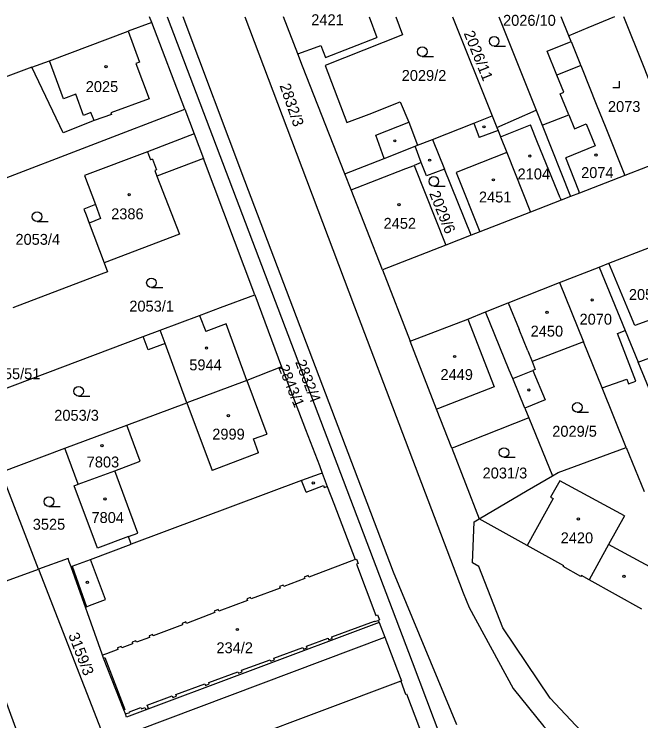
# Model space of a CAD drawing. Extents: x -564952 to -564307, y -1202373 to -1201847.
# Drawn here: x -564730.1 to -564632.5, y -1201959.8 to -1201849.7 of the extents above; entities that cross this region are included whole.
import ezdxf

# ---------------------------------------------------------------- set-up
doc = ezdxf.new("R2010")
doc.units = 0
for name, color, linetype in [('Hranice parcel', 7, 'Continuous'), ('Parcelní čísla', 7, 'Continuous'), ('Vnitřní kresba', 7, 'Continuous'), ('Značky budov', 7, 'Continuous'), ('Značky kultur', 7, 'Continuous')]:
    doc.layers.add(name, color=color, linetype=linetype)

msp = doc.modelspace()

# ---------------------------------------------------------------- linework, layer by layer
at = {"layer": 'Hranice parcel'}
for p, q in [((-564708.7, -1201850.95), (-564709.04, -1201850.07)), ((-564706.28, -1201850.07), (-564668.12, -1201950.64)), ((-564694.16, -1201875.63), (-564703.8, -1201850.07)), ((-564694.18, -1201850.07), (-564686.16, -1201871.23)), ((-564661.81, -1201850.07), (-564655.61, -1201865.52)), ((-564654.61, -1201850.07), (-564648.79, -1201864.64)), ((-564643.69, -1201853.02), (-564644.88, -1201850.07)), ((-564708.7, -1201850.95), (-564712.36, -1201852.32)), ((-564703.52, -1201864.46), (-564708.7, -1201850.95)), ((-564724.64, -1201856.92), (-564712.36, -1201852.32)), ((-564712.36, -1201852.32), (-564710.6, -1201857.14)), ((-564643.32, -1201853.94), (-564643.69, -1201853.02)), ((-564727.38, -1201857.94), (-564724.64, -1201856.92)), ((-564737.23, -1201877.39), (-564703.52, -1201864.46)), ((-564703.52, -1201864.46), (-564702.07, -1201868.33)), ((-564654.9, -1201867.35), (-564648.79, -1201864.64)), ((-564648.79, -1201864.64), (-564647.86, -1201866.96)), ((-564655.61, -1201865.52), (-564654.9, -1201867.35)), ((-564647.86, -1201866.96), (-564643.4, -1201878.11)), ((-564702.07, -1201868.33), (-564709.37, -1201871.11)), ((-564702.07, -1201868.33), (-564700.62, -1201872.17)), ((-564667.27, -1201870.1), (-564664.94, -1201869.19)), ((-564664.94, -1201869.19), (-564663.07, -1201873.83)), ((-564692.64, -1201893.4), (-564700.62, -1201872.17)), ((-564658.92, -1201884.13), (-564663.07, -1201873.83)), ((-564658.92, -1201884.13), (-564662.87, -1201885.69)), ((-564662.87, -1201885.69), (-564672.74, -1201889.5)), ((-564672.74, -1201889.5), (-564668.43, -1201900.65)), ((-564645.16, -1201891.48), (-564638.96, -1201889.11)), ((-564645.16, -1201891.48), (-564641.39, -1201900.77)), ((-564692.64, -1201893.4), (-564688.47, -1201904.65)), ((-564736.45, -1201909.86), (-564710.02, -1201899.92)), ((-564703.22, -1201910.26), (-564706.62, -1201900.99)), ((-564632.88, -1201903.92), (-564624.54, -1201900.73)), ((-564625.61, -1201921.62), (-564632.88, -1201903.92)), ((-564712.58, -1201913.74), (-564703.22, -1201910.26)), ((-564650.53, -1201911.09), (-564649.91, -1201912.6)), ((-564649.91, -1201912.6), (-564646.22, -1201921.62)), ((-564722.24, -1201917.34), (-564712.58, -1201913.74)), ((-564732.16, -1201921.04), (-564722.24, -1201917.34)), ((-564720.15, -1201922.96), (-564722.24, -1201917.34)), ((-564661.94, -1201917.34), (-564657.66, -1201928.36)), ((-564634.72, -1201917.22), (-564631.93, -1201924.07)), ((-564726.36, -1201936.19), (-564732.16, -1201921.04)), ((-564720.15, -1201922.96), (-564714.47, -1201920.84)), ((-564650.19, -1201932.49), (-564657.66, -1201928.36)), ((-564711.89, -1201932.3), (-564712.33, -1201931.11)), ((-564721.74, -1201934.52), (-564726.36, -1201936.19)), ((-564673.25, -1201944.51), (-564672.37, -1201946.79)), ((-564668.12, -1201950.64), (-564653.5, -1201989.14))]:
    msp.add_line(p, q, dxfattribs=at)
for points in [[(-564678.6, -1201874.56), (-564685.18, -1201857.76), (-564685.91, -1201855.87), (-564688.16, -1201850.07)], [(-564670.64, -1201850.07), (-564669.6, -1201852.87), (-564681.68, -1201857.67), (-564678.29, -1201866.56), (-564674.81, -1201865.25), (-564669.96, -1201863.32), (-564668.61, -1201866.52), (-564667.27, -1201870.1)], [(-564636.56, -1201850.07), (-564640.71, -1201851.79), (-564643.69, -1201853.02)], [(-564626.56, -1201871.38), (-564626.65, -1201871.15), (-564630.57, -1201861.4), (-564632.05, -1201857.71), (-564635.12, -1201850.07)], [(-564647.86, -1201866.96), (-564643.7, -1201865.35), (-564645.03, -1201862.07), (-564644.46, -1201861.84), (-564645.54, -1201859.17), (-564647.04, -1201855.43), (-564643.32, -1201853.94)], [(-564643.32, -1201853.94), (-564641.99, -1201857.29), (-564641.93, -1201857.43), (-564641.83, -1201857.68), (-564641.62, -1201858.2), (-564639.41, -1201863.69)], [(-564710.6, -1201857.14), (-564711.16, -1201857.36), (-564709.11, -1201862.88), (-564715.07, -1201865.02), (-564714.96, -1201865.29), (-564717.67, -1201866.26), (-564722.49, -1201868.17), (-564727.38, -1201857.94)], [(-564727.38, -1201857.94), (-564753.52, -1201867.7), (-564747.75, -1201881.47)], [(-564639.41, -1201863.69), (-564637.92, -1201867.4), (-564634.97, -1201874.82)], [(-564664.94, -1201869.19), (-564658.51, -1201866.66), (-564655.61, -1201865.52)], [(-564654.9, -1201867.35), (-564654.72, -1201867.8), (-564654.33, -1201868.79), (-564653.36, -1201871.21), (-564649.64, -1201880.53)], [(-564678.6, -1201874.56), (-564672.48, -1201872.15), (-564667.64, -1201870.24), (-564667.27, -1201870.1)], [(-564709.37, -1201871.11), (-564719.17, -1201874.83), (-564717.48, -1201879.35), (-564719.29, -1201880.05), (-564718.94, -1201880.95), (-564718.45, -1201882.23), (-564716.1, -1201888.41)], [(-564686.16, -1201871.23), (-564677.08, -1201895.29), (-564660.17, -1201939.88), (-564659.23, -1201942.17), (-564652.34, -1201954.8), (-564647.57, -1201960.74), (-564641.3, -1201967.43), (-564636.51, -1201971.74), (-564631.4, -1201974.9), (-564623.41, -1201978.76)], [(-564626.56, -1201871.38), (-564626.5, -1201871.52), (-564627.97, -1201872.09), (-564634.97, -1201874.82)], [(-564700.62, -1201872.17), (-564707.88, -1201874.94), (-564704.36, -1201883.94), (-564716.1, -1201888.41)], [(-564663.07, -1201873.83), (-564665.89, -1201874.89), (-564666.68, -1201872.79), (-564667.81, -1201873.23), (-564662.87, -1201885.69)], [(-564672.74, -1201889.5), (-564677.63, -1201877.03), (-564678.6, -1201874.56)], [(-564634.97, -1201874.82), (-564642, -1201877.55), (-564643.4, -1201878.11)], [(-564661.15, -1201960.44), (-564670.99, -1201936.66), (-564694.16, -1201875.63)], [(-564643.4, -1201878.11), (-564644.88, -1201878.68), (-564649.64, -1201880.53)], [(-564649.64, -1201880.53), (-564657.55, -1201883.6), (-564658.92, -1201884.13)], [(-564638.96, -1201889.11), (-564637.47, -1201888.5), (-564630.43, -1201885.8)], [(-564716.1, -1201888.41), (-564715.57, -1201889.81), (-564716.6, -1201890.2), (-564730.34, -1201895.42)], [(-564638.96, -1201889.11), (-564634.9, -1201899), (-564632.88, -1201903.92)], [(-564656.68, -1201896.09), (-564653.11, -1201894.66), (-564645.16, -1201891.48)], [(-564710.02, -1201899.92), (-564707.39, -1201898.93), (-564701.23, -1201896.62), (-564697.99, -1201895.41), (-564692.64, -1201893.4)], [(-564668.43, -1201900.65), (-564659.44, -1201897.19), (-564656.68, -1201896.09)], [(-564650.53, -1201911.09), (-564652.43, -1201906.46), (-564652.96, -1201905.18), (-564656.68, -1201896.09)], [(-564706.62, -1201900.99), (-564709.25, -1201901.97), (-564710.02, -1201899.92)], [(-564661.94, -1201917.34), (-564664.31, -1201911.26), (-564668.43, -1201900.65)], [(-564641.39, -1201900.77), (-564649.41, -1201903.83), (-564648.92, -1201905.05), (-564649.28, -1201905.19), (-564647.38, -1201909.8), (-564650.53, -1201911.09)], [(-564634.72, -1201917.22), (-564638.49, -1201907.91), (-564641.39, -1201900.77)], [(-564688.47, -1201904.65), (-564693.85, -1201906.77), (-564703.22, -1201910.26)], [(-564688.47, -1201904.65), (-564688.27, -1201905.18), (-564684.73, -1201914.39)], [(-564649.91, -1201912.6), (-564661.62, -1201917.21), (-564661.94, -1201917.34)], [(-564714.47, -1201920.84), (-564710.49, -1201919.36), (-564712.58, -1201913.74)], [(-564684.73, -1201914.39), (-564682.57, -1201920.04), (-564682.13, -1201921.2)], [(-564646.22, -1201921.62), (-564645.34, -1201921.1), (-564634.72, -1201917.22)], [(-564712.33, -1201931.11), (-564710.85, -1201930.56), (-564714.47, -1201920.84)], [(-564682.13, -1201921.2), (-564682.58, -1201921.37), (-564685.33, -1201922.39), (-564711.89, -1201932.3)], [(-564682.13, -1201921.2), (-564681.34, -1201923.29), (-564680.33, -1201925.94), (-564676.99, -1201934.7), (-564676.78, -1201934.62), (-564676.52, -1201935.32), (-564676.76, -1201935.41), (-564673.74, -1201943.42), (-564673.49, -1201943.32), (-564673.2, -1201944.1), (-564673.38, -1201944.17), (-564673.25, -1201944.51)], [(-564657.66, -1201928.36), (-564650.16, -1201923.94), (-564646.22, -1201921.62)], [(-564712.33, -1201931.11), (-564717.17, -1201932.91), (-564720.79, -1201923.2), (-564720.15, -1201922.96)], [(-564653.95, -1201945.36), (-564657.69, -1201935.77), (-564658.7, -1201935.2), (-564658.45, -1201928.82), (-564657.66, -1201928.36)], [(-564721.28, -1201935.81), (-564721.1, -1201935.74), (-564718.26, -1201934.68), (-564711.89, -1201932.3)], [(-564632.28, -1201942.4), (-564640.53, -1201937.84), (-564641.72, -1201937.18), (-564641.79, -1201937.31), (-564644.55, -1201935.78), (-564644.48, -1201935.65), (-564650.19, -1201932.49)], [(-564721.28, -1201935.81), (-564721.55, -1201935.06), (-564721.74, -1201934.52)], [(-564711.3, -1202011.73), (-564714.18, -1202003.86), (-564737.5, -1201940.24), (-564726.36, -1201936.19)], [(-564726.36, -1201936.19), (-564715.86, -1201963.16), (-564672.37, -1201946.79)], [(-564673.25, -1201944.51), (-564712.62, -1201959.24), (-564712.76, -1201958.76), (-564713.05, -1201958.13), (-564716.2, -1201950.04), (-564716.38, -1201949.6), (-564716.43, -1201949.46), (-564721.28, -1201935.81)], [(-564596.05, -1201977.38), (-564604.58, -1201977.37), (-564614.37, -1201976.21), (-564623.15, -1201973.61), (-564632.26, -1201969.32), (-564640.22, -1201963.11), (-564646.58, -1201956.32), (-564653.95, -1201945.36)], [(-564672.37, -1201946.79), (-564669.95, -1201953.07), (-564669.75, -1201953.6), (-564669.89, -1201953.65)], [(-564669.89, -1201953.65), (-564706.41, -1201967.36), (-564714.12, -1201970.26), (-564699.64, -1202009.87)], [(-564669.89, -1201953.65), (-564669.13, -1201955.68), (-564668.99, -1201955.63), (-564666.96, -1201960.96)]]:
    msp.add_lwpolyline(points, dxfattribs=at)
at = {"layer": 'Vnitřní kresba'}
for p, q in [((-564674.82, -1201850.07), (-564673.59, -1201853.3)), ((-564681.62, -1201856.39), (-564673.59, -1201853.3)), ((-564685.91, -1201855.87), (-564682.73, -1201854.69)), ((-564682.73, -1201854.69), (-564682.34, -1201854.54)), ((-564682.34, -1201854.54), (-564681.62, -1201856.39)), ((-564722.45, -1201862.85), (-564724.64, -1201856.92)), ((-564641.83, -1201857.68), (-564645.54, -1201859.17)), ((-564720.54, -1201862.14), (-564722.45, -1201862.85)), ((-564719.33, -1201865.46), (-564720.54, -1201862.14)), ((-564718.17, -1201865), (-564719.33, -1201865.46)), ((-564717.67, -1201866.26), (-564718.17, -1201865)), ((-564643.7, -1201865.35), (-564642.82, -1201867.52)), ((-564673.76, -1201868.54), (-564668.61, -1201866.52)), ((-564658.51, -1201866.66), (-564657.65, -1201868.91)), ((-564654.33, -1201868.79), (-564649.67, -1201866.89)), ((-564648.54, -1201869.67), (-564649.67, -1201866.89)), ((-564642.82, -1201867.52), (-564640.97, -1201866.77)), ((-564640.97, -1201866.77), (-564639.58, -1201870.19)), ((-564672.48, -1201872.15), (-564673.76, -1201868.54)), ((-564654.72, -1201867.8), (-564657.65, -1201868.91)), ((-564645.03, -1201878.28), (-564648.54, -1201869.67)), ((-564666.68, -1201872.79), (-564667.64, -1201870.24)), ((-564639.58, -1201870.19), (-564644.16, -1201872.06)), ((-564709.37, -1201871.11), (-564708.87, -1201872.38)), ((-564653.36, -1201871.21), (-564661.25, -1201874.37)), ((-564708.59, -1201872.27), (-564708.87, -1201872.38)), ((-564708.59, -1201872.27), (-564707.95, -1201873.91)), ((-564642.14, -1201877.18), (-564644.16, -1201872.06)), ((-564707.95, -1201873.91), (-564708.23, -1201874.02)), ((-564708.23, -1201874.02), (-564707.88, -1201874.94)), ((-564673.62, -1201875.48), (-564669.1, -1201873.73)), ((-564669.1, -1201873.73), (-564667.81, -1201873.23)), ((-564661.25, -1201874.37), (-564657.55, -1201883.6)), ((-564677.63, -1201877.03), (-564673.62, -1201875.48)), ((-564642, -1201877.55), (-564642.14, -1201877.18)), ((-564645.03, -1201878.28), (-564644.88, -1201878.68)), ((-564717.48, -1201879.35), (-564716.66, -1201881.54)), ((-564716.66, -1201881.54), (-564718.45, -1201882.23)), ((-564634.33, -1201895.99), (-564637.47, -1201888.5)), ((-564653.11, -1201894.66), (-564651.43, -1201898.82)), ((-564633.4, -1201898.2), (-564634.33, -1201895.99)), ((-564626.54, -1201895.68), (-564633.4, -1201898.2)), ((-564701.23, -1201896.62), (-564700.28, -1201899.11)), ((-564659.44, -1201897.19), (-564655.32, -1201907.74)), ((-564697.07, -1201897.94), (-564700.28, -1201899.11)), ((-564693.85, -1201906.77), (-564697.07, -1201897.94)), ((-564706.62, -1201900.99), (-564707.39, -1201898.93)), ((-564650.09, -1201902.15), (-564651.43, -1201898.82)), ((-564636.11, -1201899.46), (-564634.9, -1201899)), ((-564633.26, -1201906.88), (-564636.11, -1201899.46)), ((-564650.09, -1201902.15), (-564649.41, -1201903.83)), ((-564652.43, -1201906.46), (-564649.28, -1201905.19)), ((-564693.85, -1201906.77), (-564690.77, -1201915.12)), ((-564638.49, -1201907.91), (-564634.63, -1201906.56)), ((-564634.63, -1201906.56), (-564634.38, -1201907.27)), ((-564634.38, -1201907.27), (-564633.26, -1201906.88)), ((-564655.32, -1201907.74), (-564663.98, -1201911.13)), ((-564703.22, -1201910.26), (-564699.3, -1201920.79)), ((-564663.98, -1201911.13), (-564664.31, -1201911.26)), ((-564692.84, -1201915.88), (-564690.77, -1201915.12)), ((-564692.04, -1201918.06), (-564692.84, -1201915.88)), ((-564692.04, -1201918.06), (-564699.3, -1201920.79)), ((-564684.61, -1201924.17), (-564685.33, -1201922.39)), ((-564645.1, -1201922.41), (-564646.52, -1201924.96)), ((-564635.02, -1201927.88), (-564645.1, -1201922.41)), ((-564684.61, -1201924.17), (-564681.92, -1201923.16)), ((-564681.92, -1201923.16), (-564681.81, -1201923.46)), ((-564681.81, -1201923.46), (-564681.34, -1201923.29)), ((-564646.14, -1201925.17), (-564650.19, -1201932.49)), ((-564646.52, -1201924.96), (-564646.14, -1201925.17)), ((-564635.02, -1201927.88), (-564637.48, -1201932.32)), ((-564637.48, -1201932.32), (-564640.53, -1201937.84)), ((-564634.32, -1201934.04), (-564637.48, -1201932.32)), ((-564715.89, -1201940.91), (-564718.26, -1201934.68)), ((-564629.21, -1201936.85), (-564634.32, -1201934.04)), ((-564721.1, -1201935.74), (-564718.88, -1201942.05)), ((-564677.48, -1201934.89), (-564684.23, -1201937.44)), ((-564676.99, -1201934.7), (-564677.48, -1201934.89)), ((-564684.84, -1201937.67), (-564688.12, -1201938.91)), ((-564684.32, -1201937.2), (-564684.93, -1201937.43)), ((-564684.93, -1201937.43), (-564684.84, -1201937.67)), ((-564684.23, -1201937.44), (-564684.32, -1201937.2)), ((-564688.21, -1201938.67), (-564688.79, -1201938.89)), ((-564688.79, -1201938.89), (-564688.7, -1201939.13)), ((-564688.12, -1201938.91), (-564688.21, -1201938.67)), ((-564688.7, -1201939.13), (-564693.2, -1201940.83)), ((-564718.41, -1201941.87), (-564715.89, -1201940.91)), ((-564693.78, -1201941.05), (-564698.24, -1201942.74)), ((-564693.29, -1201940.6), (-564693.87, -1201940.82)), ((-564693.87, -1201940.82), (-564693.78, -1201941.05)), ((-564693.2, -1201940.83), (-564693.29, -1201940.6)), ((-564718.88, -1201942.05), (-564718.41, -1201941.87)), ((-564698.85, -1201942.97), (-564703.28, -1201944.64)), ((-564698.33, -1201942.5), (-564698.94, -1201942.73)), ((-564698.94, -1201942.73), (-564698.85, -1201942.97)), ((-564698.24, -1201942.74), (-564698.33, -1201942.5)), ((-564703.37, -1201944.41), (-564703.97, -1201944.64)), ((-564703.28, -1201944.64), (-564703.37, -1201944.41)), ((-564680.64, -1201946.75), (-564673.97, -1201944.28)), ((-564673.97, -1201944.28), (-564673.93, -1201944.37)), ((-564673.93, -1201944.37), (-564673.38, -1201944.17)), ((-564703.88, -1201944.87), (-564708.45, -1201946.6)), ((-564703.97, -1201944.64), (-564703.88, -1201944.87)), ((-564708.54, -1201946.37), (-564709.12, -1201946.59)), ((-564709.12, -1201946.59), (-564709.03, -1201946.82)), ((-564708.45, -1201946.6), (-564708.54, -1201946.37)), ((-564680.55, -1201946.98), (-564680.64, -1201946.75)), ((-564711.68, -1201947.82), (-564713.36, -1201948.46)), ((-564711.16, -1201947.36), (-564711.76, -1201947.59)), ((-564711.76, -1201947.59), (-564711.68, -1201947.82)), ((-564711.08, -1201947.59), (-564711.16, -1201947.36)), ((-564709.03, -1201946.82), (-564711.08, -1201947.59)), ((-564684.58, -1201948.21), (-564681.22, -1201946.97)), ((-564681.22, -1201946.97), (-564681.13, -1201947.2)), ((-564681.13, -1201947.2), (-564680.55, -1201946.98)), ((-564713.96, -1201948.69), (-564715.76, -1201949.37)), ((-564713.45, -1201948.22), (-564714.05, -1201948.45)), ((-564714.05, -1201948.45), (-564713.96, -1201948.69)), ((-564713.36, -1201948.46), (-564713.45, -1201948.22)), ((-564689.65, -1201950.09), (-564685.14, -1201948.42)), ((-564685.14, -1201948.42), (-564685.05, -1201948.65)), ((-564685.05, -1201948.65), (-564684.49, -1201948.44)), ((-564684.49, -1201948.44), (-564684.58, -1201948.21)), ((-564715.76, -1201949.37), (-564716.38, -1201949.6)), ((-564716.2, -1201950.04), (-564716.02, -1201949.97)), ((-564716.02, -1201949.97), (-564712.87, -1201958.06)), ((-564689.56, -1201950.32), (-564689.65, -1201950.09)), ((-564694.71, -1201951.96), (-564690.21, -1201950.3)), ((-564690.21, -1201950.3), (-564690.13, -1201950.53)), ((-564690.13, -1201950.53), (-564689.56, -1201950.32)), ((-564699.81, -1201953.85), (-564695.27, -1201952.17)), ((-564695.27, -1201952.17), (-564695.18, -1201952.41)), ((-564695.18, -1201952.41), (-564694.62, -1201952.2)), ((-564694.62, -1201952.2), (-564694.71, -1201951.96)), ((-564704.94, -1201955.75), (-564700.4, -1201954.07)), ((-564700.4, -1201954.07), (-564700.31, -1201954.31)), ((-564700.31, -1201954.31), (-564699.72, -1201954.09)), ((-564699.72, -1201954.09), (-564699.81, -1201953.85)), ((-564709.39, -1201957.41), (-564705.5, -1201955.96)), ((-564705.5, -1201955.96), (-564705.42, -1201956.2)), ((-564705.42, -1201956.2), (-564704.85, -1201955.99)), ((-564704.85, -1201955.99), (-564704.94, -1201955.75)), ((-564712.14, -1201958.41), (-564710.38, -1201957.77)), ((-564710.38, -1201957.77), (-564710.31, -1201957.97)), ((-564710.31, -1201957.97), (-564709.75, -1201957.76)), ((-564709.75, -1201957.76), (-564709.64, -1201958.07)), ((-564709.21, -1201957.91), (-564709.39, -1201957.41)), ((-564712.87, -1201958.06), (-564713.05, -1201958.13)), ((-564712.76, -1201958.76), (-564712.1, -1201958.52)), ((-564712.1, -1201958.52), (-564712.14, -1201958.41)), ((-564709.64, -1201958.07), (-564709.21, -1201957.91))]:
    msp.add_line(p, q, dxfattribs=at)
at = {"layer": 'Značky budov'}
for centre in [(-564715.81, -1201857.86), (-564656.91, -1201867.22), (-564670.8, -1201869.41), (-564649.76, -1201871.78), (-564639.45, -1201871.62), (-564665.38, -1201872.42), (-564655.44, -1201875.49), (-564712.21, -1201877.8), (-564670.16, -1201879.35), (-564640.04, -1201894.22), (-564647.08, -1201896.15), (-564700.16, -1201901.71), (-564661.49, -1201903.03), (-564649.92, -1201908.25), (-564696.74, -1201912.27), (-564716.46, -1201916.93), (-564683.52, -1201922.74), (-564715.99, -1201925.24), (-564642.18, -1201928.36), (-564635.09, -1201937.32), (-564718.72, -1201938.23), (-564695.34, -1201945.59)]:
    msp.add_circle(centre, 0.175, dxfattribs=at)
at = {"layer": 'Značky kultur'}
for p, q in [((-564655.32, -1201854.63), (-564653.57, -1201854.63)), ((-564666.53, -1201856.26), (-564664.78, -1201856.26)), ((-564635.8, -1201861.08), (-564635.8, -1201860.08)), ((-564636.8, -1201861.08), (-564635.8, -1201861.08)), ((-564664.72, -1201876.48), (-564662.97, -1201876.48)), ((-564726.57, -1201881.99), (-564724.82, -1201881.99)), ((-564708.74, -1201892.3), (-564706.99, -1201892.3)), ((-564720.1, -1201909.2), (-564718.35, -1201909.2)), ((-564642.36, -1201911.72), (-564640.61, -1201911.72)), ((-564653.79, -1201918.75), (-564652.04, -1201918.75)), ((-564724.72, -1201926.41), (-564722.97, -1201926.41))]:
    msp.add_line(p, q, dxfattribs=at)
for centre in [(-564655.32, -1201853.88), (-564666.53, -1201855.51), (-564664.72, -1201875.73), (-564726.57, -1201881.24), (-564708.74, -1201891.55), (-564720.1, -1201908.45), (-564642.36, -1201910.97), (-564653.79, -1201918), (-564724.72, -1201925.66)]:
    msp.add_circle(centre, 0.75, dxfattribs=at)

# ---------------------------------------------------------------- texts
at = {"layer": 'Parcelní čísla'}
for s, p in [('2421', (-564683.83, -1201851.38)), ('2026/10', (-564653.93, -1201851.47)), ('2029/2', (-564669.73, -1201860.07)), ('2025', (-564718.98, -1201861.8)), ('2073', (-564637.58, -1201864.91)), ('2104', (-564651.67, -1201875.42)), ('2074', (-564641.76, -1201875.21)), ('2451', (-564657.69, -1201879.02)), ('2386', (-564715.02, -1201881.64)), ('2452', (-564672.55, -1201883.12)), ('2053/4', (-564729.94, -1201885.62)), ('2056', (-564634.32, -1201894.22)), ('2053/1', (-564712.19, -1201896.03)), ('2070', (-564642.01, -1201898.07)), ('2450', (-564649.63, -1201899.93)), ('5944', (-564702.84, -1201905.19)), ('2055/51', (-564734.27, -1201906.57)), ('2449', (-564663.69, -1201906.7)), ('2053/3', (-564723.89, -1201913.05)), ('2029/5', (-564646.26, -1201915.54)), ('2999', (-564699.26, -1201915.99)), ('7803', (-564718.83, -1201920.33)), ('2031/3', (-564657.12, -1201922.05)), ('7804', (-564718.09, -1201928.99)), ('3525', (-564727.24, -1201930.04)), ('2420', (-564644.95, -1201932.16)), ('234/2', (-564698.61, -1201949.29))]:
    msp.add_text(s, height=1.7, dxfattribs=at).set_placement(p)
for s, rotation, p in [('2026/11', 292, (-564660.09, -1201852.63)), ('2832/3', 289, (-564688.79, -1201860.78)), ('2029/6', 292, (-564665.47, -1201877.61)), ('2832/4', 291, (-564686.36, -1201903.9)), ('2843/1', 292, (-564689.01, -1201904.7)), ('3159/3', 291, (-564721.73, -1201946.46))]:
    msp.add_text(s, height=1.7, rotation=rotation, dxfattribs=at).set_placement(p)

doc.saveas('drawing.dxf')
